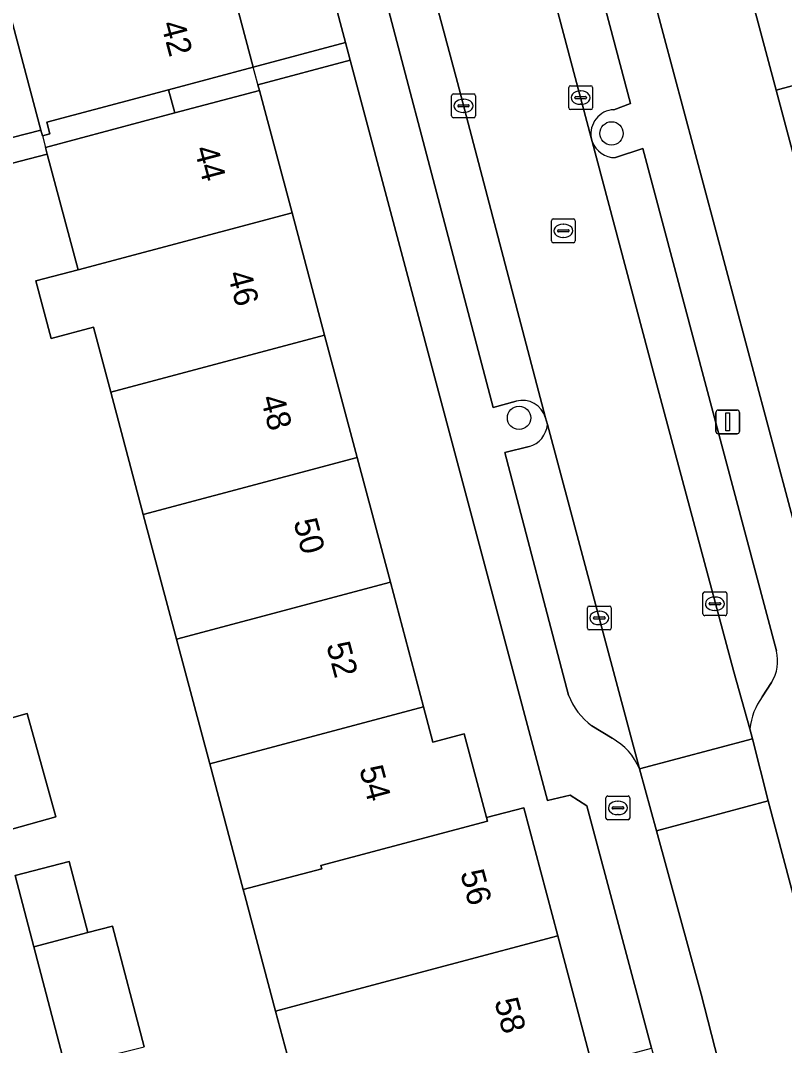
# Model space of a CAD drawing. Extents: x 162542 to 163147, y 380779 to 381521.
# Drawn here: x 162754.32 to 162786.35, y 380876.19 to 380919.18 of the extents above; entities that cross this region are included whole.
import ezdxf

# ---------------------------------------------------------------- set-up
doc = ezdxf.new("R2010")
doc.units = 0
for name, color, linetype in [('IMGEO_Boom', 7, 'Continuous'), ('IMGEO_Brandkraan', 7, 'Continuous'), ('IMGEO_Erf', 7, 'Continuous'), ('IMGEO_Kolk', 7, 'Continuous'), ('IMGEO_Lichtmast', 7, 'Continuous'), ('IMGEO_Pand', 7, 'Continuous'), ('IMGEO_Pand_nummerreeks', 7, 'Continuous'), ('IMGEO_Pand_overbouw', 7, 'Continuous'), ('IMGEO_Parkeervlak_open', 7, 'Continuous'), ('IMGEO_Rijbaan_lokaal_open', 7, 'Continuous'), ('IMGEO_Rioolput', 7, 'Continuous'), ('IMGEO_Voetpad_open', 7, 'Continuous')]:
    doc.layers.add(name, color=color, linetype=linetype)

msp = doc.modelspace()

# ---------------------------------------------------------------- linework, layer by layer
at = {"layer": 'IMGEO_Boom'}
for centre in [(162779.096, 380914.45), (162775.218, 380902.517)]:
    msp.add_circle(centre, 0.489, dxfattribs=at)
at = {"layer": 'IMGEO_Brandkraan'}
for p, q in [((162778.938, 380886.657), (162779.79, 380886.657)), ((162778.863, 380885.731), (162778.863, 380886.583)), ((162779.351, 380886.437), (162779.376, 380886.437)), ((162779.864, 380886.583), (162779.864, 380885.731)), ((162779.122, 380886.151), (162779.122, 380886.163)), ((162779.56, 380886.114), (162779.162, 380886.114)), ((162779.165, 380886.2), (162779.563, 380886.2)), ((162779.374, 380885.877), (162779.349, 380885.877)), ((162779.606, 380886.163), (162779.606, 380886.151)), ((162779.79, 380885.657), (162778.938, 380885.657))]:
    msp.add_line(p, q, dxfattribs=at)
for points in [[(162778.938, 380886.657), (162779.79, 380886.657)], [(162778.863, 380885.731), (162778.863, 380886.583)], [(162779.864, 380886.583), (162779.864, 380885.731)], [(162779.79, 380885.657), (162778.938, 380885.657)]]:
    msp.add_lwpolyline(points, dxfattribs=at)
for centre, radius, start, end in [((162778.94, 380886.581), 0.0765, 91.552, 178.448), ((162778.94, 380886.581), 0.0765, 91.552, 178.448), ((162779.788, 380886.581), 0.0765, 1.552, 88.448), ((162779.788, 380886.581), 0.0765, 1.552, 88.448), ((162779.162, 380886.16), 0.0403, 85.8775, 175.7526), ((162779.159, 380886.15), 0.0366, 178.938, 274.7102), ((162779.563, 380886.157), 0.043, 264.8664, 352.4533), ((162779.567, 380886.162), 0.0386, 1.7309, 96.639), ((162778.94, 380885.733), 0.0765, 181.552, 268.448), ((162778.94, 380885.733), 0.0765, 181.552, 268.448), ((162779.788, 380885.733), 0.0765, 271.552, 358.448), ((162779.788, 380885.733), 0.0765, 271.552, 358.448)]:
    msp.add_arc(centre, radius, start, end, dxfattribs=at)
for centre, major_axis, ratio, start_param, end_param in [((162779.35, 380886.157), (-0.387, 0.002), 0.722429, 4.712389, 7.853982), ((162779.375, 380886.157), (-0.39, 0.002), 0.717154, 1.570796, 4.712389)]:
    msp.add_ellipse(centre, major_axis=major_axis, ratio=ratio, start_param=start_param, end_param=end_param, dxfattribs=at)
at = {"layer": 'IMGEO_Erf'}
for points in [[(162751.467, 380980.135), (162747.619, 380979.111), (162747.702, 380978.798), (162749.067, 380973.666), (162750.432, 380968.535), (162751.797, 380963.403), (162753.162, 380958.272), (162754.527, 380953.141), (162755.892, 380948.009), (162757.257, 380942.877), (162758.623, 380937.745), (162759.988, 380932.613), (162761.352, 380927.483), (162762.717, 380922.351), (162764.079, 380917.227), (162767.943, 380918.262)], [(162787.389, 380911.023), (162785.994, 380916.261), (162784.652, 380921.296), (162780.832, 380920.278), (162787.754, 380894.316), (162788.858, 380889.82), (162787.979, 380889.585), (162787.726, 380889.027), (162790.444, 380878.831), (162792.701, 380879.433), (162791.368, 380884.436), (162789.872, 380890.054), (162791.407, 380890.462), (162790.439, 380894.095), (162791.801, 380894.457), (162791.485, 380895.645), (162790.126, 380900.745), (162788.743, 380905.938)], [(162768.14, 380917.522), (162764.275, 380916.492), (162764.339, 380916.251), (162765.705, 380911.12), (162767.07, 380905.988), (162768.435, 380900.856), (162769.826, 380895.629), (162771.217, 380890.4), (162771.611, 380888.918), (162772.925, 380889.268), (162773.861, 380885.752), (162775.416, 380886.166), (162776.846, 380880.79), (162778.276, 380875.416), (162780.774, 380876.082), (162778.067, 380886.244), (162777.36, 380886.698), (162776.41, 380886.464)]]:
    msp.add_lwpolyline(points, close=True, dxfattribs=at)
for points in [[(162742.476, 380922.454), (162743.819, 380917.317), (162745.009, 380917.634), (162745.669, 380915.067), (162742.272, 380914.194), (162742.744, 380912.36), (162744.07, 380911.741), (162755.176, 380914.586), (162753.745, 380919.961)], [(162765.5, 380875.822), (162765.016, 380877.639), (162763.725, 380882.487), (162763.66, 380882.73), (162762.253, 380888.013), (162760.861, 380893.241), (162759.469, 380898.468), (162758.103, 380903.599), (162757.379, 380906.316), (162755.606, 380905.844), (162754.964, 380908.258), (162756.736, 380908.73), (162755.444, 380913.578), (162743.692, 380910.528)], [(162752.459, 380889.521), (162754.608, 380890.112), (162755.802, 380885.778), (162753.605, 380885.173)], [(162754.094, 380883.318), (162756.358, 380883.915), (162757.145, 380880.929), (162758.177, 380881.201), (162759.51, 380876.143)]]:
    msp.add_lwpolyline(points, dxfattribs=at)
at = {"layer": 'IMGEO_Kolk'}
for p, q in [((162777.301, 380915.522), (162777.301, 380916.374)), ((162777.376, 380916.448), (162778.228, 380916.448)), ((162778.302, 380916.374), (162778.302, 380915.522)), ((162772.392, 380915.179), (162772.392, 380916.031)), ((162772.467, 380916.105), (162773.319, 380916.105)), ((162772.88, 380915.885), (162772.905, 380915.885)), ((162773.393, 380916.031), (162773.393, 380915.179)), ((162777.56, 380915.942), (162777.56, 380915.954)), ((162777.998, 380915.905), (162777.6, 380915.905)), ((162777.603, 380915.991), (162778.001, 380915.991)), ((162777.789, 380916.228), (162777.814, 380916.228)), ((162778.044, 380915.954), (162778.044, 380915.942)), ((162772.651, 380915.599), (162772.651, 380915.611)), ((162773.089, 380915.562), (162772.691, 380915.562)), ((162772.694, 380915.648), (162773.092, 380915.648)), ((162773.135, 380915.611), (162773.135, 380915.599)), ((162778.228, 380915.448), (162777.376, 380915.448)), ((162777.812, 380915.668), (162777.787, 380915.668)), ((162773.319, 380915.105), (162772.467, 380915.105)), ((162772.903, 380915.325), (162772.878, 380915.325)), ((162782.929, 380894.295), (162782.929, 380895.147)), ((162783.004, 380895.221), (162783.856, 380895.221)), ((162783.417, 380895.001), (162783.442, 380895.001)), ((162783.93, 380895.147), (162783.93, 380894.295)), ((162778.083, 380893.698), (162778.083, 380894.55)), ((162778.158, 380894.624), (162779.01, 380894.624)), ((162778.571, 380894.404), (162778.596, 380894.404)), ((162779.084, 380894.55), (162779.084, 380893.698)), ((162783.188, 380894.715), (162783.188, 380894.727)), ((162783.626, 380894.678), (162783.228, 380894.678)), ((162783.231, 380894.764), (162783.629, 380894.764)), ((162783.44, 380894.441), (162783.415, 380894.441)), ((162783.672, 380894.727), (162783.672, 380894.715)), ((162778.342, 380894.118), (162778.342, 380894.13)), ((162778.78, 380894.081), (162778.382, 380894.081)), ((162778.385, 380894.167), (162778.783, 380894.167)), ((162778.826, 380894.13), (162778.826, 380894.118)), ((162783.856, 380894.221), (162783.004, 380894.221)), ((162779.01, 380893.624), (162778.158, 380893.624)), ((162778.594, 380893.844), (162778.569, 380893.844))]:
    msp.add_line(p, q, dxfattribs=at)
for points in [[(162777.301, 380915.522), (162777.301, 380916.374)], [(162777.376, 380916.448), (162778.228, 380916.448)], [(162778.302, 380916.374), (162778.302, 380915.522)], [(162772.392, 380915.179), (162772.392, 380916.031)], [(162772.467, 380916.105), (162773.319, 380916.105)], [(162773.393, 380916.031), (162773.393, 380915.179)], [(162778.228, 380915.448), (162777.376, 380915.448)], [(162773.319, 380915.105), (162772.467, 380915.105)], [(162782.929, 380894.295), (162782.929, 380895.147)], [(162783.004, 380895.221), (162783.856, 380895.221)], [(162783.93, 380895.147), (162783.93, 380894.295)], [(162778.083, 380893.698), (162778.083, 380894.55)], [(162778.158, 380894.624), (162779.01, 380894.624)], [(162779.084, 380894.55), (162779.084, 380893.698)], [(162783.856, 380894.221), (162783.004, 380894.221)], [(162779.01, 380893.624), (162778.158, 380893.624)]]:
    msp.add_lwpolyline(points, dxfattribs=at)
for centre, radius, start, end in [((162777.378, 380916.372), 0.0765, 91.552, 178.448), ((162777.378, 380916.372), 0.0765, 91.552, 178.448), ((162778.226, 380916.372), 0.0765, 1.552, 88.448), ((162778.226, 380916.372), 0.0765, 1.552, 88.448), ((162772.469, 380916.029), 0.0765, 91.552, 178.448), ((162772.469, 380916.029), 0.0765, 91.552, 178.448), ((162773.317, 380916.029), 0.0765, 1.552, 88.448), ((162773.317, 380916.029), 0.0765, 1.552, 88.448), ((162777.6, 380915.951), 0.0403, 85.8775, 175.7526), ((162777.597, 380915.941), 0.0366, 178.938, 274.7102), ((162778.001, 380915.948), 0.043, 264.8664, 352.4533), ((162778.005, 380915.953), 0.0386, 1.7309, 96.639), ((162772.691, 380915.608), 0.0403, 85.8775, 175.7526), ((162772.688, 380915.598), 0.0366, 178.938, 274.7102), ((162773.092, 380915.605), 0.043, 264.8664, 352.4533), ((162773.096, 380915.61), 0.0386, 1.7309, 96.639), ((162777.378, 380915.524), 0.0765, 181.552, 268.448), ((162777.378, 380915.524), 0.0765, 181.552, 268.448), ((162778.226, 380915.524), 0.0765, 271.552, 358.448), ((162778.226, 380915.524), 0.0765, 271.552, 358.448), ((162772.469, 380915.181), 0.0765, 181.552, 268.448), ((162772.469, 380915.181), 0.0765, 181.552, 268.448), ((162773.317, 380915.181), 0.0765, 271.552, 358.448), ((162773.317, 380915.181), 0.0765, 271.552, 358.448), ((162783.006, 380895.145), 0.0765, 91.552, 178.448), ((162783.006, 380895.145), 0.0765, 91.552, 178.448), ((162783.854, 380895.145), 0.0765, 1.552, 88.448), ((162783.854, 380895.145), 0.0765, 1.552, 88.448), ((162778.16, 380894.548), 0.0765, 91.552, 178.448), ((162778.16, 380894.548), 0.0765, 91.552, 178.448), ((162779.008, 380894.548), 0.0765, 1.552, 88.448), ((162779.008, 380894.548), 0.0765, 1.552, 88.448), ((162783.228, 380894.724), 0.0403, 85.8775, 175.7526), ((162783.225, 380894.714), 0.0366, 178.938, 274.7102), ((162783.629, 380894.721), 0.043, 264.8664, 352.4533), ((162783.633, 380894.726), 0.0386, 1.7309, 96.639), ((162778.382, 380894.127), 0.0403, 85.8775, 175.7526), ((162778.379, 380894.117), 0.0366, 178.938, 274.7102), ((162778.783, 380894.124), 0.043, 264.8664, 352.4533), ((162778.787, 380894.129), 0.0386, 1.7309, 96.639), ((162783.006, 380894.297), 0.0765, 181.552, 268.448), ((162783.006, 380894.297), 0.0765, 181.552, 268.448), ((162783.854, 380894.297), 0.0765, 271.552, 358.448), ((162783.854, 380894.297), 0.0765, 271.552, 358.448), ((162778.16, 380893.7), 0.0765, 181.552, 268.448), ((162778.16, 380893.7), 0.0765, 181.552, 268.448), ((162779.008, 380893.7), 0.0765, 271.552, 358.448), ((162779.008, 380893.7), 0.0765, 271.552, 358.448)]:
    msp.add_arc(centre, radius, start, end, dxfattribs=at)
for centre, major_axis, ratio, start_param, end_param in [((162772.879, 380915.605), (-0.387, 0.002), 0.722429, 4.712389, 7.853982), ((162772.904, 380915.605), (-0.39, 0.002), 0.717154, 1.570796, 4.712389), ((162777.788, 380915.948), (-0.387, 0.002), 0.722429, 4.712389, 7.853982), ((162777.813, 380915.948), (-0.39, 0.002), 0.717154, 1.570796, 4.712389), ((162783.416, 380894.721), (-0.387, 0.002), 0.722429, 4.712389, 7.853982), ((162783.441, 380894.721), (-0.39, 0.002), 0.717154, 1.570796, 4.712389), ((162778.57, 380894.124), (-0.387, 0.002), 0.722429, 4.712389, 7.853982), ((162778.595, 380894.124), (-0.39, 0.002), 0.717154, 1.570796, 4.712389)]:
    msp.add_ellipse(centre, major_axis=major_axis, ratio=ratio, start_param=start_param, end_param=end_param, dxfattribs=at)
at = {"layer": 'IMGEO_Lichtmast'}
for p, q in [((162783.468, 380901.947), (162783.468, 380902.747)), ((162783.468, 380902.747), (162783.468, 380901.947)), ((162783.568, 380902.847), (162784.358, 380902.847)), ((162784.358, 380902.847), (162783.568, 380902.847)), ((162784.458, 380902.747), (162784.458, 380901.947)), ((162784.458, 380901.947), (162784.458, 380902.747)), ((162784.358, 380901.847), (162783.568, 380901.847)), ((162783.568, 380901.847), (162784.358, 380901.847))]:
    msp.add_line(p, q, dxfattribs=at)
msp.add_lwpolyline([(162783.888, 380902.722), (162784.038, 380902.722), (162784.038, 380901.972), (162783.888, 380901.972), (162783.888, 380902.722)], dxfattribs=at)
for centre, start, end in [((162783.568, 380902.747), 90, 180), ((162783.568, 380902.747), 90, 180), ((162784.358, 380902.747), 0, 90), ((162784.358, 380902.747), 360, 90), ((162783.568, 380901.947), 180, 270), ((162783.568, 380901.947), 180, 270), ((162784.358, 380901.947), 270, 0), ((162784.358, 380901.947), 270, 0)]:
    msp.add_arc(centre, 0.1, start, end, dxfattribs=at)
at = {"layer": 'IMGEO_Pand'}
for points in [[(162796.44, 380924.766), (162793.556, 380923.998), (162793.626, 380923.737), (162784.64, 380921.342), (162784.652, 380921.296), (162785.994, 380916.261), (162794.967, 380918.7), (162797.847, 380919.483)], [(162762.717, 380922.351), (162753.745, 380919.961), (162755.176, 380914.586), (162755.24, 380914.345), (162755.56, 380914.43), (162755.432, 380914.915), (162760.529, 380916.272), (162764.079, 380917.227)], [(162794.967, 380918.7), (162785.994, 380916.261), (162787.389, 380911.023), (162795.997, 380913.48), (162796.096, 380913.108), (162796.43, 380913.206)], [(162764.339, 380916.251), (162760.787, 380915.305), (162755.371, 380913.852), (162755.444, 380913.578), (162756.736, 380908.73), (162765.705, 380911.12)], [(162758.103, 380903.599), (162767.07, 380905.988), (162765.705, 380911.12), (162756.736, 380908.73), (162754.964, 380908.258), (162755.606, 380905.844), (162757.379, 380906.316)], [(162758.103, 380903.599), (162759.469, 380898.468), (162768.435, 380900.856), (162767.07, 380905.988)], [(162768.435, 380900.856), (162759.469, 380898.468), (162760.861, 380893.241), (162769.826, 380895.629)], [(162762.253, 380888.013), (162771.217, 380890.4), (162769.826, 380895.629), (162760.861, 380893.241)], [(162754.608, 380890.112), (162752.459, 380889.521), (162752.68, 380888.684), (162753.605, 380885.173), (162755.802, 380885.778)], [(162762.253, 380888.013), (162763.66, 380882.73), (162766.947, 380883.606), (162766.911, 380883.74), (162773.9, 380885.605), (162773.861, 380885.752), (162772.925, 380889.268), (162771.611, 380888.918), (162771.217, 380890.4)], [(162767.818, 380878.388), (162776.846, 380880.79), (162775.416, 380886.166), (162773.861, 380885.752), (162773.9, 380885.605), (162766.911, 380883.74), (162766.947, 380883.606), (162763.66, 380882.73), (162763.725, 380882.487), (162765.016, 380877.639)], [(162754.094, 380883.318), (162754.881, 380880.333), (162757.145, 380880.929), (162756.358, 380883.915)], [(162758.177, 380881.201), (162757.145, 380880.929), (162754.881, 380880.333), (162756.159, 380875.485), (162756.214, 380875.274), (162757.597, 380875.663), (162759.51, 380876.143)], [(162776.846, 380880.79), (162767.818, 380878.388), (162765.016, 380877.639), (162765.5, 380875.822), (162765.828, 380874.589), (162766.446, 380872.269), (162769.256, 380873.012), (162773.445, 380874.131), (162778.276, 380875.416)]]:
    msp.add_lwpolyline(points, close=True, dxfattribs=at)
at = {"layer": 'IMGEO_Pand_overbouw'}
for points in [[(162764.079, 380917.227), (162760.529, 380916.272), (162760.787, 380915.305), (162764.339, 380916.251)], [(162760.787, 380915.305), (162760.529, 380916.272), (162755.432, 380914.915), (162755.56, 380914.43), (162755.24, 380914.345), (162755.371, 380913.852)]]:
    msp.add_lwpolyline(points, close=True, dxfattribs=at)
at = {"layer": 'IMGEO_Parkeervlak_open'}
for points in [[(162779.19, 380915.442), (162779.888, 380915.697), (162776.12, 380929.96), (162774.215, 380929.454), (162778.249, 380914.26)], [(162776.334, 380902.519), (162772.635, 380916.59), (162769.53, 380928.208), (162769.244, 380929.276)], [(162768.553, 380928.156), (162767.576, 380927.887), (162774.135, 380902.949), (162775.099, 380903.218)], [(162778.29, 380914.105), (162780.844, 380904.471), (162784.223, 380891.867), (162784.888, 380889.476)], [(162780.412, 380913.819), (162779.257, 380913.435)], [(162786.011, 380892.739), (162780.412, 380913.819)], [(162780.272, 380887.798), (162776.409, 380902.238)], [(162775.649, 380901.314), (162774.621, 380901.071), (162777.293, 380890.893)], [(162785.41, 380890.823), (162785.808, 380891.423)], [(162778.273, 380889.599), (162779.125, 380889.081)]]:
    msp.add_lwpolyline(points, dxfattribs=at)
for centre, radius, start, end in [((162779.235, 380914.44), 1.003, 92.5912, 190.3616), ((162779.235, 380914.437), 1.002, 199.3325, 271.2341), ((162775.359, 380902.236), 1.015, 16.1591, 104.8218), ((162775.355, 380902.33), 1.058, 286.1229, 355.0017), ((162784.318, 380892.326), 1.742, 328.7652, 13.6967), ((162779.912, 380891.858), 2.791, 200.2339, 234.0424), ((162787.877, 380889.092), 3.013, 144.9482, 172.6863), ((162777.762, 380886.708), 2.736, 23.4688, 60.1245)]:
    msp.add_arc(centre, radius, start, end, dxfattribs=at)
at = {"layer": 'IMGEO_Rijbaan_lokaal_open'}
for points in [[(162778.29, 380914.105), (162778.249, 380914.26), (162774.215, 380929.454), (162769.53, 380928.208), (162772.635, 380916.59), (162776.334, 380902.519), (162776.409, 380902.238), (162780.272, 380887.798), (162785.006, 380889.053), (162784.888, 380889.476), (162784.223, 380891.867), (162780.844, 380904.471)], [(162785.006, 380889.053), (162780.272, 380887.798), (162780.982, 380885.195), (162785.664, 380886.45)], [(162789.002, 380873.892), (162788.444, 380876.005), (162788.238, 380876.778), (162785.664, 380886.45), (162780.982, 380885.195), (162782.851, 380878.347), (162783.57, 380875.561), (162784.325, 380872.639), (162784.433, 380872.219), (162789.507, 380853.33), (162789.924, 380851.717), (162790.179, 380850.73), (162794.883, 380852.068), (162794.551, 380853.257), (162794.102, 380855.017), (162792.548, 380860.454), (162790.496, 380868.229)]]:
    msp.add_lwpolyline(points, close=True, dxfattribs=at)
msp.add_lwpolyline([(162752.093, 380874.397), (162754.996, 380875.175), (162756.159, 380875.485), (162754.881, 380880.333), (162754.094, 380883.318)], dxfattribs=at)
at = {"layer": 'IMGEO_Rioolput'}
for p, q in [((162776.576, 380909.936), (162776.576, 380910.788)), ((162776.651, 380910.862), (162777.503, 380910.862)), ((162777.577, 380910.788), (162777.577, 380909.936)), ((162776.835, 380910.356), (162776.835, 380910.368)), ((162777.273, 380910.319), (162776.875, 380910.319)), ((162776.878, 380910.405), (162777.276, 380910.405)), ((162777.064, 380910.642), (162777.089, 380910.642)), ((162777.319, 380910.368), (162777.319, 380910.356)), ((162777.503, 380909.862), (162776.651, 380909.862)), ((162777.087, 380910.082), (162777.062, 380910.082))]:
    msp.add_line(p, q, dxfattribs=at)
for points in [[(162776.576, 380909.936), (162776.576, 380910.788)], [(162776.651, 380910.862), (162777.503, 380910.862)], [(162777.577, 380910.788), (162777.577, 380909.936)], [(162777.503, 380909.862), (162776.651, 380909.862)]]:
    msp.add_lwpolyline(points, dxfattribs=at)
for centre, radius, start, end in [((162776.653, 380910.786), 0.0765, 91.552, 178.448), ((162776.653, 380910.786), 0.0765, 91.552, 178.448), ((162777.501, 380910.786), 0.0765, 1.552, 88.448), ((162777.501, 380910.786), 0.0765, 1.552, 88.448), ((162776.875, 380910.365), 0.0403, 85.8775, 175.7526), ((162776.872, 380910.355), 0.0366, 178.938, 274.7102), ((162777.276, 380910.362), 0.043, 264.8664, 352.4533), ((162777.28, 380910.367), 0.0386, 1.7309, 96.639), ((162776.653, 380909.938), 0.0765, 181.552, 268.448), ((162776.653, 380909.938), 0.0765, 181.552, 268.448), ((162777.501, 380909.938), 0.0765, 271.552, 358.448), ((162777.501, 380909.938), 0.0765, 271.552, 358.448)]:
    msp.add_arc(centre, radius, start, end, dxfattribs=at)
for centre, major_axis, ratio, start_param, end_param in [((162777.063, 380910.362), (-0.387, 0.002), 0.722429, 4.712389, 7.853982), ((162777.088, 380910.362), (-0.39, 0.002), 0.717154, 1.570796, 4.712389)]:
    msp.add_ellipse(centre, major_axis=major_axis, ratio=ratio, start_param=start_param, end_param=end_param, dxfattribs=at)
at = {"layer": 'IMGEO_Voetpad_open'}
for points in [[(162784.888, 380889.476), (162785.006, 380889.053), (162785.664, 380886.45), (162788.238, 380876.778), (162790.799, 380877.498), (162790.444, 380878.831), (162787.726, 380889.027), (162787.979, 380889.585), (162788.858, 380889.82), (162787.754, 380894.316), (162780.832, 380920.278), (162780.617, 380921.086), (162763.955, 380983.585), (162763.686, 380984.593), (162759.578, 381000), (162755.726, 381014.447), (162754.046, 381014.881), (162751.366, 381025.19), (162751.014, 381026.543), (162750.404, 381028.836), (162749.506, 381032.166), (162746.399, 381043.845)], [(162739.036, 381041.753), (162736.762, 381041.139), (162739.873, 381029.488), (162740.737, 381026.252), (162741.338, 381024.003), (162741.713, 381022.565), (162744.463, 381012.029), (162743.026, 381011.614), (162746.28, 381000), (162748.205, 380992.388), (162751.174, 380981.237), (162751.467, 380980.135), (162767.943, 380918.262), (162768.14, 380917.522), (162776.41, 380886.464), (162777.36, 380886.698), (162778.067, 380886.244), (162780.774, 380876.082), (162781.077, 380874.945), (162783.57, 380875.561), (162782.851, 380878.347), (162780.982, 380885.195), (162780.272, 380887.798)], [(162772.351, 380940.392), (162773.303, 380940.622), (162775.443, 380932.523), (162776.12, 380929.96), (162779.888, 380915.697), (162779.19, 380915.442)], [(162775.099, 380903.218), (162774.135, 380902.949), (162767.576, 380927.887), (162768.553, 380928.156)], [(162739.41, 380921.187), (162740.842, 380916.043), (162741.747, 380912.787), (162742.267, 380910.784), (162743.54, 380911.114), (162743.692, 380910.528), (162755.444, 380913.578), (162755.371, 380913.852), (162760.787, 380915.305), (162764.339, 380916.251), (162764.275, 380916.492), (162768.14, 380917.522), (162767.943, 380918.262), (162764.079, 380917.227), (162760.529, 380916.272), (162755.432, 380914.915), (162755.56, 380914.43), (162755.24, 380914.345), (162755.176, 380914.586), (162744.07, 380911.741), (162742.744, 380912.36), (162742.272, 380914.194), (162741.62, 380916.731), (162740.298, 380921.873)], [(162778.249, 380914.26), (162778.29, 380914.105)], [(162779.257, 380913.435), (162780.412, 380913.819), (162786.011, 380892.739)], [(162776.409, 380902.238), (162776.334, 380902.519)], [(162777.293, 380890.893), (162774.621, 380901.071), (162775.649, 380901.314)], [(162785.808, 380891.423), (162785.41, 380890.823)], [(162779.125, 380889.081), (162778.273, 380889.599)]]:
    msp.add_lwpolyline(points, dxfattribs=at)
for centre, radius, start, end in [((162779.235, 380914.44), 1.003, 92.5912, 190.3616), ((162779.235, 380914.437), 1.002, 199.3325, 271.2341), ((162775.359, 380902.236), 1.015, 16.1591, 104.8218), ((162775.355, 380902.33), 1.058, 286.1229, 355.0017), ((162784.318, 380892.326), 1.742, 328.7652, 13.6967), ((162779.912, 380891.858), 2.791, 200.2339, 234.0424), ((162787.877, 380889.092), 3.013, 144.9482, 172.6863), ((162777.762, 380886.708), 2.736, 23.4688, 60.1245)]:
    msp.add_arc(centre, radius, start, end, dxfattribs=at)

# ---------------------------------------------------------------- texts
at = {"layer": 'IMGEO_Pand_nummerreeks'}
for s, rotation, p in [('42', 284.8967, (162760.204, 380919.044)), ('44', 284.8967, (162761.598, 380913.802)), ('46', 284.8963, (162762.992, 380908.563)), ('48', 284.8963, (162764.378, 380903.349)), ('50', 284.8963, (162765.757, 380898.165)), ('52', 284.8963, (162767.135, 380892.988)), ('54', 284.8963, (162768.515, 380887.802)), ('56', 284.8982, (162772.749, 380883.434)), ('58', 284.8967, (162774.179, 380878.056))]:
    msp.add_text(s, height=1, rotation=rotation, dxfattribs=at).set_placement(p)

doc.saveas('drawing.dxf')
